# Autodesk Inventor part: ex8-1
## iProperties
Author: Administrator
Created: 2001-03
Part Number: ex8-1
Document SubType Name: Modeling
Designer: Administrator
Control State: 0
Master: False
Checked Out: False
PropertySet Name: Design Tracking Control
Shininess: 20.0
Length Units: 11272
Angle Units: 11286
Time Units: 11279
Mass Units: 11290
Length Display Precision: 3
Angle Display Precision: 2
Compacted: False
PropertySet Name: _Private Model Information
Density: 0.0
Volumn: 0.0
Area: 0.0
PropertySet Name: Model Information
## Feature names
1. Extrusion1
2. Extrusion2
